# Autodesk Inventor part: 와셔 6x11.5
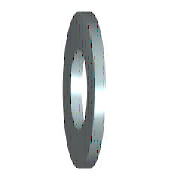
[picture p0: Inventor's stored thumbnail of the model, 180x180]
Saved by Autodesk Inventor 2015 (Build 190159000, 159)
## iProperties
IsCustomPart: 1
Created: 2012-02
Part Number: 와셔 6x11.5
Material: 강철, 연강
Description: 평면 와셔
Document SubType Name: Modeling
Standard: KS B 1326
Designer: mduedu
Standards Organization: KS
Language: ko-KR
Size Designation: 6x11.5
Categories: <MemberInstance><Categories><Category DisplayName="조임쇠" InternalName="e4da775c-781d-43d5-af7c-5136215cf5a6" Mnemonic="FSTN"><Category DisplayName="와셔" InternalN
Density: 1 g/cm^3
Appearance: 분홍색
Author: mduedu
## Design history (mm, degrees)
sketch "스케치"
  geometry: C1 r 5.75 at (0, 0); C2 r 3.2 at (0, 0); 1 further point
  constraints: 2 centre point, 2 coincident
  dimensions: "d0" = 6.4 diameter of C2 (= SD1); "d1" = 11.5 diameter of C1 (= SD2)
extrude "본체" new body sketch "스케치" distance "d2" = 1.6 (= SD); taper "d3" = 0 deg
workaxis "Work Axis1"
workplane "Work Plane1"
body "Solid1"
other parameters: "SD1" = 6.4 [user parameter; used in 1 equation term], "SD2" = 11.5 [user parameter; used in 1 equation term], "SD" = 1.6 [user parameter; used in 1 equation term], "d4" = 0, "d5" = 0, "d6" = 0, "d7" = 0, "NND" = 6 [user parameter]
